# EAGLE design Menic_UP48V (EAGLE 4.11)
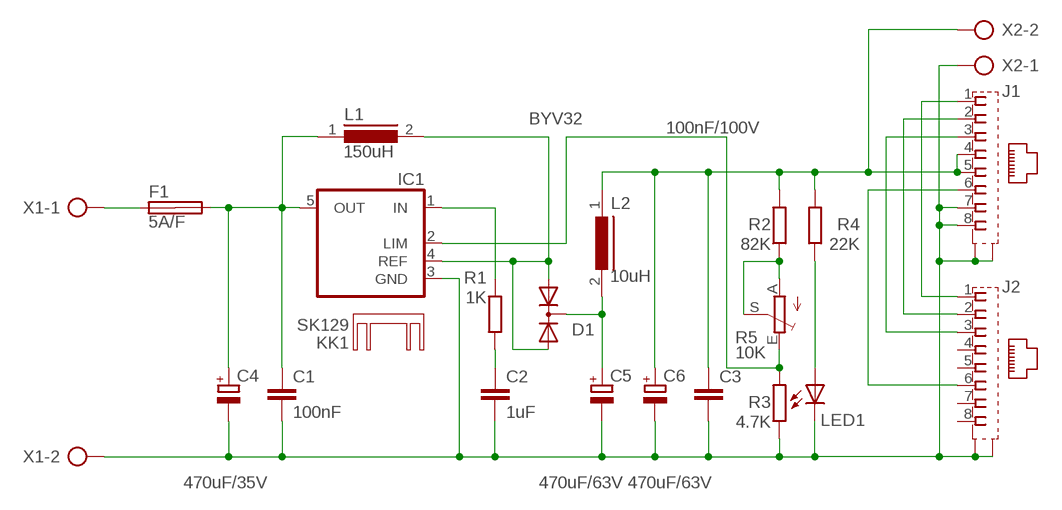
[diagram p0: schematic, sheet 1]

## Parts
C1  100nF  C-EU025_050-025X075  [C025_050-025X075]
C2  1uF  C-EU025_050-025X075  [C025_050-025X075]
C3  100nF/100V  C-EU025_050-025X075  [C025_050-025X075]
C4  470uF/35V  CPOL-EUE5-10.5  [E5-10,5]
C5  470uF/63V  CPOL-EUE5-10.5  [E5-10,5]
C6  470uF/63V  CPOL-EUE5-10.5  [E5-10,5]
D1  BYV32  [TO220ABS]
F1  5A/F  SHK20L  [SHK20L]
IC1  L200  [L200S]
J1  556591-1  [556591-1]
J2  556591-1  [556591-1]
KK1  SK129  [SK129]
L1  150uH  SFT1240  [SFT1240]
L2  10uH  82114R  [82114R]
LED1  LED3MM  [LED3MM]
R1  1K  R-EU_0207/10  [0207/10]
R2  82K  R-EU_0207/10  [0207/10]
R3  4.7K  R-EU_0207/10  [0207/10]
R4  22K  R-EU_0207/10  [0207/10]
R5  10K  TRIM_EU-CA6V  [CA6V]
X1  AK500/2  [AK500/2]
X2  AK500/2  [AK500/2]

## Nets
N$1: F1.1A X1.1
N$2: J1.1 J2.1
N$3: C1.1 C4.+ F1.2A IC1.5(OUT) L1.1
N$5: D1.A1 D1.A2 IC1.4(REF) L1.2
N$6: IC1.1(IN) R1.2
N$7: C2.1 R1.1
N$8: C5.+ D1.C L2.2
N$9: LED1.A R4.1
N$11: R2.1 R5.A R5.S
N$12: IC1.2(LIM) R3.2 R5.E
N$13: J1.2 J2.2
N$14: C1.2 C2.2 C3.2 C4.- C5.- C6.- IC1.3(GND) J1.7 J1.8 J1.G1(S1) J1.G2(S2) J2.G1(S1) J2.G2(S2) LED1.K(C) R3.1 X1.2 X2.1
N$15: J1.3 J2.3
N$16: J1.6 J2.6
N$19: C3.1 C6.+ J1.4 J1.5 L2.1 R2.2 R4.2 X2.2
Unconnected: F1.1B F1.2B J2.4 J2.5 J2.7 J2.8

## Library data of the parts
C1-C3 = rcl:C-EU: CAPACITOR, European symbol
C4-C6 = rcl:CPOL-EU: POLARIZED CAPACITOR, European symbol
D1 = diode:BYV32: DIODE 2 x Si diode 200 V, 20 A/230 Apeak, 25 ns
F1 = fuse:SHK20L: FUSE HOLDER 5 x 20 mm, SH contact, SHH1 Schukat, E1073 Buerklin
IC1 = v-reg:L200: VOLTAGE REGULATOR
J1 J2 = con-amp:556591-1: AMP connector
KK1 = heatsink:SK129: HEATSINK
L1 = inductors:SFT1240: INDUCTOR
L2 = inductors:82114R: INDUCTOR
LED1 = led:LED: LED
R1-R4 = rcl:R-EU_: RESISTOR, European symbol
R5 = pot:TRIM_EU-: POTENTIOMETER
X1 X2 = con-ptr500:AK500/2: CONNECTOR

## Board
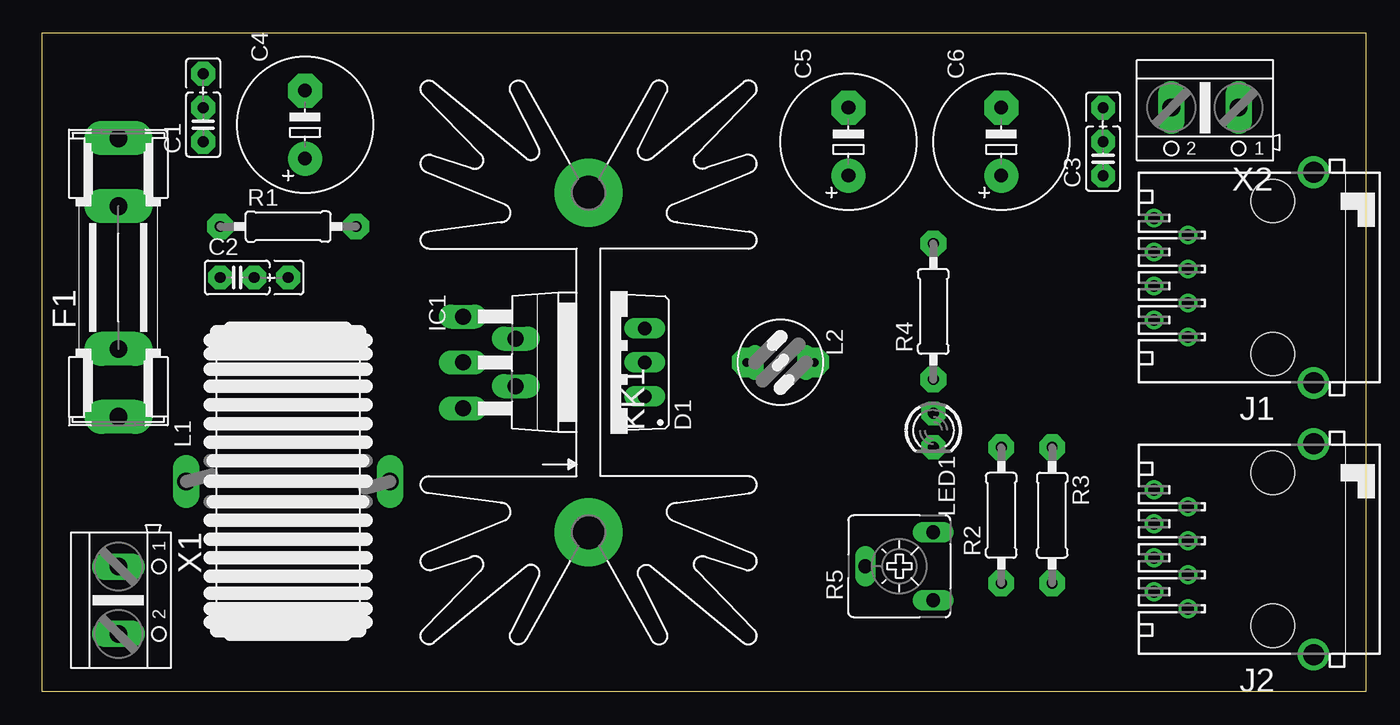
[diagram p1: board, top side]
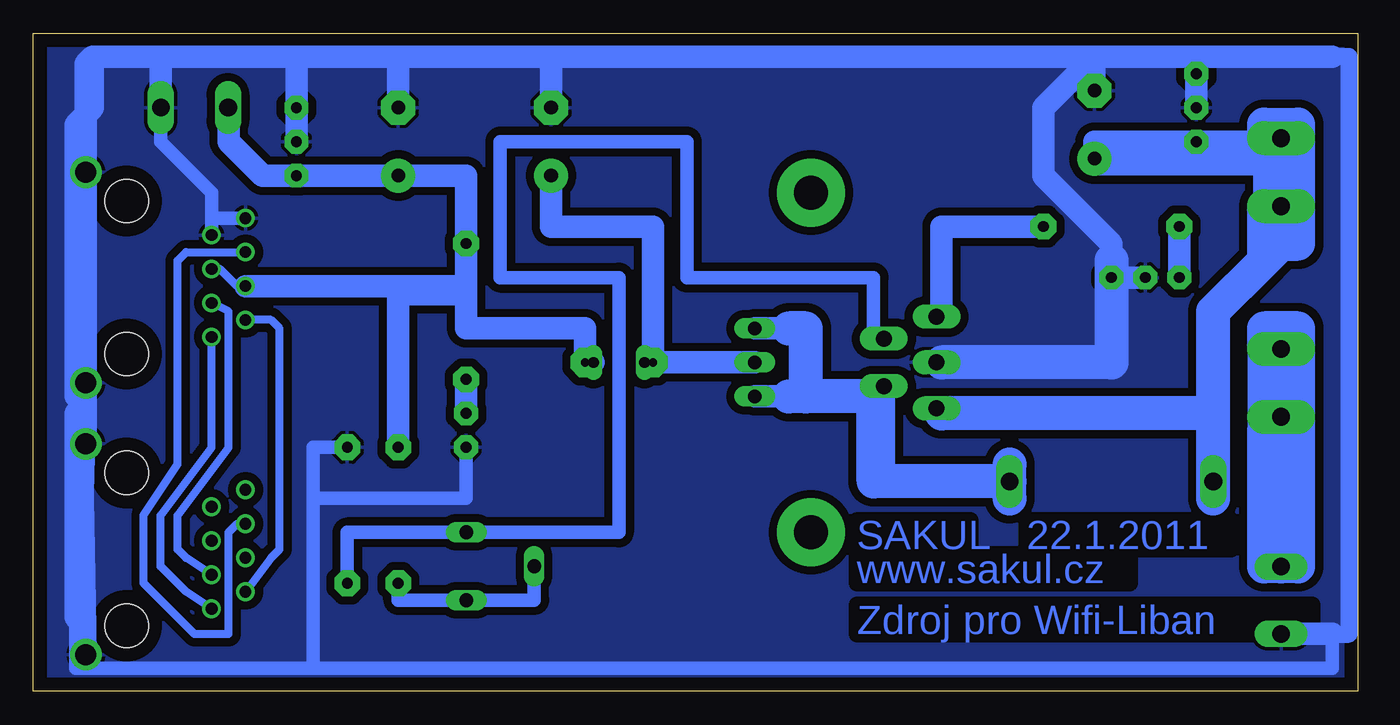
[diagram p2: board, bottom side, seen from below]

Size 99.04 x 49.2 mm. Coordinates in mm from the lower left corner, seen from the top.
Outline: 0,0 99.04,0 99.04,49.2 0,49.2 0,0
Copper layers (1*16): Top 0.035mm / dielectric 1.5mm / Bottom 0.035mm
Design rules "default": minimum track width 10mil, minimum drill 24mil, track to track 8mil, track to pad 8mil, pad to pad 8mil, via to via 8mil, smd to smd 8mil, copper to edge 40mil, drill to drill 8mil, minimum pad ring 10mil, minimum via ring 8mil, stop-mask expansion 4mil, vias tented up to drill 0mil, thermal gap 10mil

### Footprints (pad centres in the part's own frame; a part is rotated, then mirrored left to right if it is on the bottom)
C025_050-025X075 = drill 0.813 pad 1.778 octagon: 1 -1.27,0; 2 1.27,0; 3 3.81,0
E5-10,5 = drill 1.016 pad 2.54 round: + -2.54,0 | drill 1.016 pad 2.54 octagon: - 2.54,0
TO220ABS = drill 1.016 long: A1 -2.54,-2.54; A2 2.54,-2.54; C 0,-2.54
SHK20L = drill 1.321 pad 2.54 long: 1A -10.414,0; 1B -5.334,0; 2A 10.414,0; 2B 5.334,0
L200S = drill 1.194 long: 1 -3.429,-8.509; 2 -1.778,-4.572; 3 0,-8.509; 4 1.778,-4.572; 5 3.429,-8.509
556591-1 = drill 0.889 round: 1 -4.445,6.35; 2 -3.175,8.89; 3 -1.905,6.35; 4 -0.635,8.89; 5 0.635,6.35; 6 1.905,8.89; 7 3.175,6.35; 8 4.445,8.89 | drill 1.575 pad 2.184 round: G1 -7.874,-3.048; G2 7.874,-3.048 | hole 3.251: -5.715,0; 5.715,0
SK129 = drill 2.54 pad 5.08 round: A2,5 -12.7,-0.889; B2,5 12.7,-0.889
SFT1240 = drill 1.321 long: 1 -7.62,0; 2 7.62,0
82114R = drill 0.813 long: 1 0,1.905; 2 0,-1.905
LED3MM = drill 0.813 pad 1.778 octagon: A -1.27,0; K 1.27,0
0207/10 = drill 0.813 pad 1.93 octagon: 1 -5.08,0; 2 5.08,0
CA6V = drill 1.016 long: A -2.54,-2.54; E 2.54,-2.54; S 0,2.54
AK500/2 = drill 1.321 long: 1 -2.515,0; 2 2.515,0

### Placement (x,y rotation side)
C1  12.06,42.38 90 top
C2  14.6,30.95 0 top
C3  79.37,39.84 90 top
C4  19.68,42.38 90 top
C5  60.32,41.11 90 top
C6  71.75,41.11 90 top
D1  42.54,24.6 90 top
F1  5.71,30.95 90 top
IC1  40,24.6 270 top
J1  92.07,30.95 90 top
J2  92.07,10.63 90 top
KK1  40,24.6 90 top
L1  18.41,15.71 0 top
L2  55.24,24.6 270 top
LED1  66.67,19.52 270 top
R1  18.41,34.76 0 top
R2  71.75,13.17 90 top
R3  75.56,13.17 270 top
R4  66.67,28.41 90 top
R5  64.13,9.36 90 top
X1  5.71,6.82 270 top
X2  86.99,43.65 180 top

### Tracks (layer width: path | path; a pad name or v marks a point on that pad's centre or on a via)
N$1
  Bottom 1.676: 5.71,20.79 F1.1A | 5.71,9.36 X1.1 | 5.71,20.79 5.71,10.63 | 5.71,20.79 5.71,24.6 5.71,25.87 6.98,25.87 | 6.98,19.52 5.71,19.52 5.71,20.79
  Bottom 2.54: 5.71,9.36 5.71,10.63 5.71,24.6 | 4.44,25.87 4.44,9.36 6.98,9.36 6.98,19.52 6.98,25.87 | 4.44,25.87 6.98,25.87 | 4.44,25.87 4.44,27.14 6.98,27.14 6.98,25.87
N$2
  Bottom 0.61: J1.1 85.72,18.25 89.53,13.17 89.53,9.36 87.62,7.46 J2.1
N$3
  Bottom 1.676: F1.2A 5.71,41.11 5.71,36.03 6.98,36.03 6.98,39.84 6.98,41.11 C1.1 19.68,41.11 C4.+ | 10.79,21.17 IC1.5 | L1.1 10.79,20.79 10.79,21.17 | 10.79,21.17 10.79,28.41
  Bottom 2.54: 6.98,32.22 6.98,36.03 | 6.98,32.22 10.79,28.41 10.79,20.79 | 10.79,14.44 10.79,20.79 | 10.79,20.79 31.11,20.79 | 6.98,39.84 C4.+ | 6.98,39.84 5.71,39.84 4.44,41.11 | 4.44,41.11 4.44,33.49 5.71,33.49 | 6.98,32.22 5.71,33.49 | 5.71,33.49 5.71,41.11 6.98,41.11 | 4.44,41.11 4.44,42.38 6.98,42.38 6.98,39.84
N$5
  Bottom 1.676: L1.2 34.92,15.71 35.43,16.22 IC1.4 36.19,22.82 36.19,22.06 | 42.54,22.06 D1.A1 | 42.54,27.14 D1.A2
  Bottom 2.54: L1.2 26.03,16.98 | 26.03,14.44 L1.2 | L1.2 36.19,15.71 36.19,22.06 41.27,22.06 | 41.27,22.06 42.54,22.06 | 41.27,22.06 41.27,27.14 42.54,27.14
N$6
  Bottom 1.676: R1.2 31.11,34.76 31.11,29.68 | 31.11,29.68 31.11,28.41 | IC1.1 31.11,28.03 31.11,29.68
N$7
  Bottom 1.676: C2.1 R1.1
N$8  (via drill 0.61 pad 2.18)
  Bottom 1.27: 51.43,24.6 L2.2
  Bottom 1.676: C5.+ 60.32,34.76 52.7,34.76 52.7,25.87 | 52.7,25.87 v52.7,24.6 51.43,24.6 D1.C | 52.7,25.87 52.7,27.14
N$9
  Bottom 1.676: LED1.A R4.1
N$11
  Bottom 1.016: R5.S 61.59,6.82 R5.A 71.75,6.82 R2.1
N$12
  Bottom 1.016: IC1.2 36.19,26.38 36.19,30.95 50.16,30.95 50.16,41.11 64.13,41.11 64.13,30.95 55.24,30.95 55.24,11.9 R5.E 75.56,11.9 R3.2
N$13
  Bottom 0.61: J1.2 81.27,27.77 80.64,27.14 80.64,10.63 81.27,10 J2.2
N$14
  Bottom 1.016: 78.1,1.74 95.88,1.74 95.88,5.55 | R3.1 78.1,18.25 78.1,14.44 | 78.1,1.74 78.1,14.44 | 78.1,1.74 1.9,1.74 1.9,4.28 | 85.72,36.03 J1.7 | 85.72,36.03 85.72,37.3 89.53,41.11 89.53,43.65 X2.1 | J1.8 85.72,35.39 85.72,36.03 | LED1.K 66.67,14.44 78.1,14.44
  Bottom 1.27: 1.9,47.46 0.63,47.46 0.63,4.28 1.9,4.28 1.9,4.3
  Bottom 1.676: 1.9,4.3 X1.2 | 1.9,47.46 12.06,47.46 | 19.68,47.46 C4.- | 12.06,47.46 C1.2 | 12.06,47.46 19.68,47.46 | 19.68,47.46 23.49,43.65 23.49,38.57 18.41,33.49 18.41,32.22 18.41,30.95 | 18.41,30.95 C2.2 | 31.11,24.6 IC1.3 | 18.41,30.95 18.41,24.6 | 19.68,47.46 60.32,47.46 | 60.32,47.46 C5.- | 60.32,47.46 71.75,47.46 | 71.75,47.46 C6.- | 71.75,47.46 79.37,47.46 | 79.37,47.46 C3.2 | 89.53,47.46 94.61,47.46 | 79.37,47.46 89.53,47.46 | 94.61,47.46 94.61,43.65 95.88,42.38 95.88,28.41 | J2.G2 95.12,46.95 94.61,47.46 | J2.G1 95.63,28.16 95.88,28.41 | 95.88,28.41 95.88,22.06 95.12,21.3 J1.G2 95.63,21.04 95.88,20.79 95.88,5.55 95.63,5.3 J1.G1 | 89.53,47.46 89.53,43.65
  Bottom 2.54: 31.11,24.6 18.41,24.6 18.41,32.22
  pour Bottom (isolate 0.61): 98.42,0.47 -0.64,0.47 -0.64,48.73 98.42,48.73
N$15
  Bottom 0.61: J2.3 87.62,10 88.26,10.63 88.26,13.17 84.45,18.25 84.45,28.41 J1.3
N$16
  Bottom 0.61: J1.6 87.62,32.85 88.26,32.22 88.26,16.98 90.8,13.17 90.8,8.09 86.99,4.28 84.45,4.28 84.45,11.9 83.81,12.54 J2.6
N$19  (via drill 0.61 pad 2.18)
  Bottom 0.61: J1.5 85.08,31.58 83.81,30.31 J1.4
  Bottom 1.676: 66.67,38.57 C6.+ C3.1 81.91,38.57 | 66.67,38.57 R4.2 66.67,29.68 | 66.67,29.68 66.67,27.14 57.78,27.14 v57.78,24.6 L2.1 | 81.91,38.57 84.45,41.11 84.45,43.65 X2.2 | R2.2 71.75,29.68 66.67,29.68 | 66.67,38.57 81.91,38.57 | J1.4 66.67,30.31 66.67,29.68

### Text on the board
Bottom: 22.1.2011 | SAKUL | www.sakul.cz | Zdroj pro Wifi-Liban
